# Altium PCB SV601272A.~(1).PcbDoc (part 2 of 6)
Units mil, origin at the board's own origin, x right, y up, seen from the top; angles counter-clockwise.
Board outline 8300 x 9520 mil, 8 copper layers (Top Layer, Signal Layer 1, Signal Layer 2, Signal Layer 3, Signal Layer 4, Signal Layer 5, Signal Layer 6, Bottom Layer), stack 59.2 mil thick; 551 components, 303 nets, 1611 pads, 1923 vias.
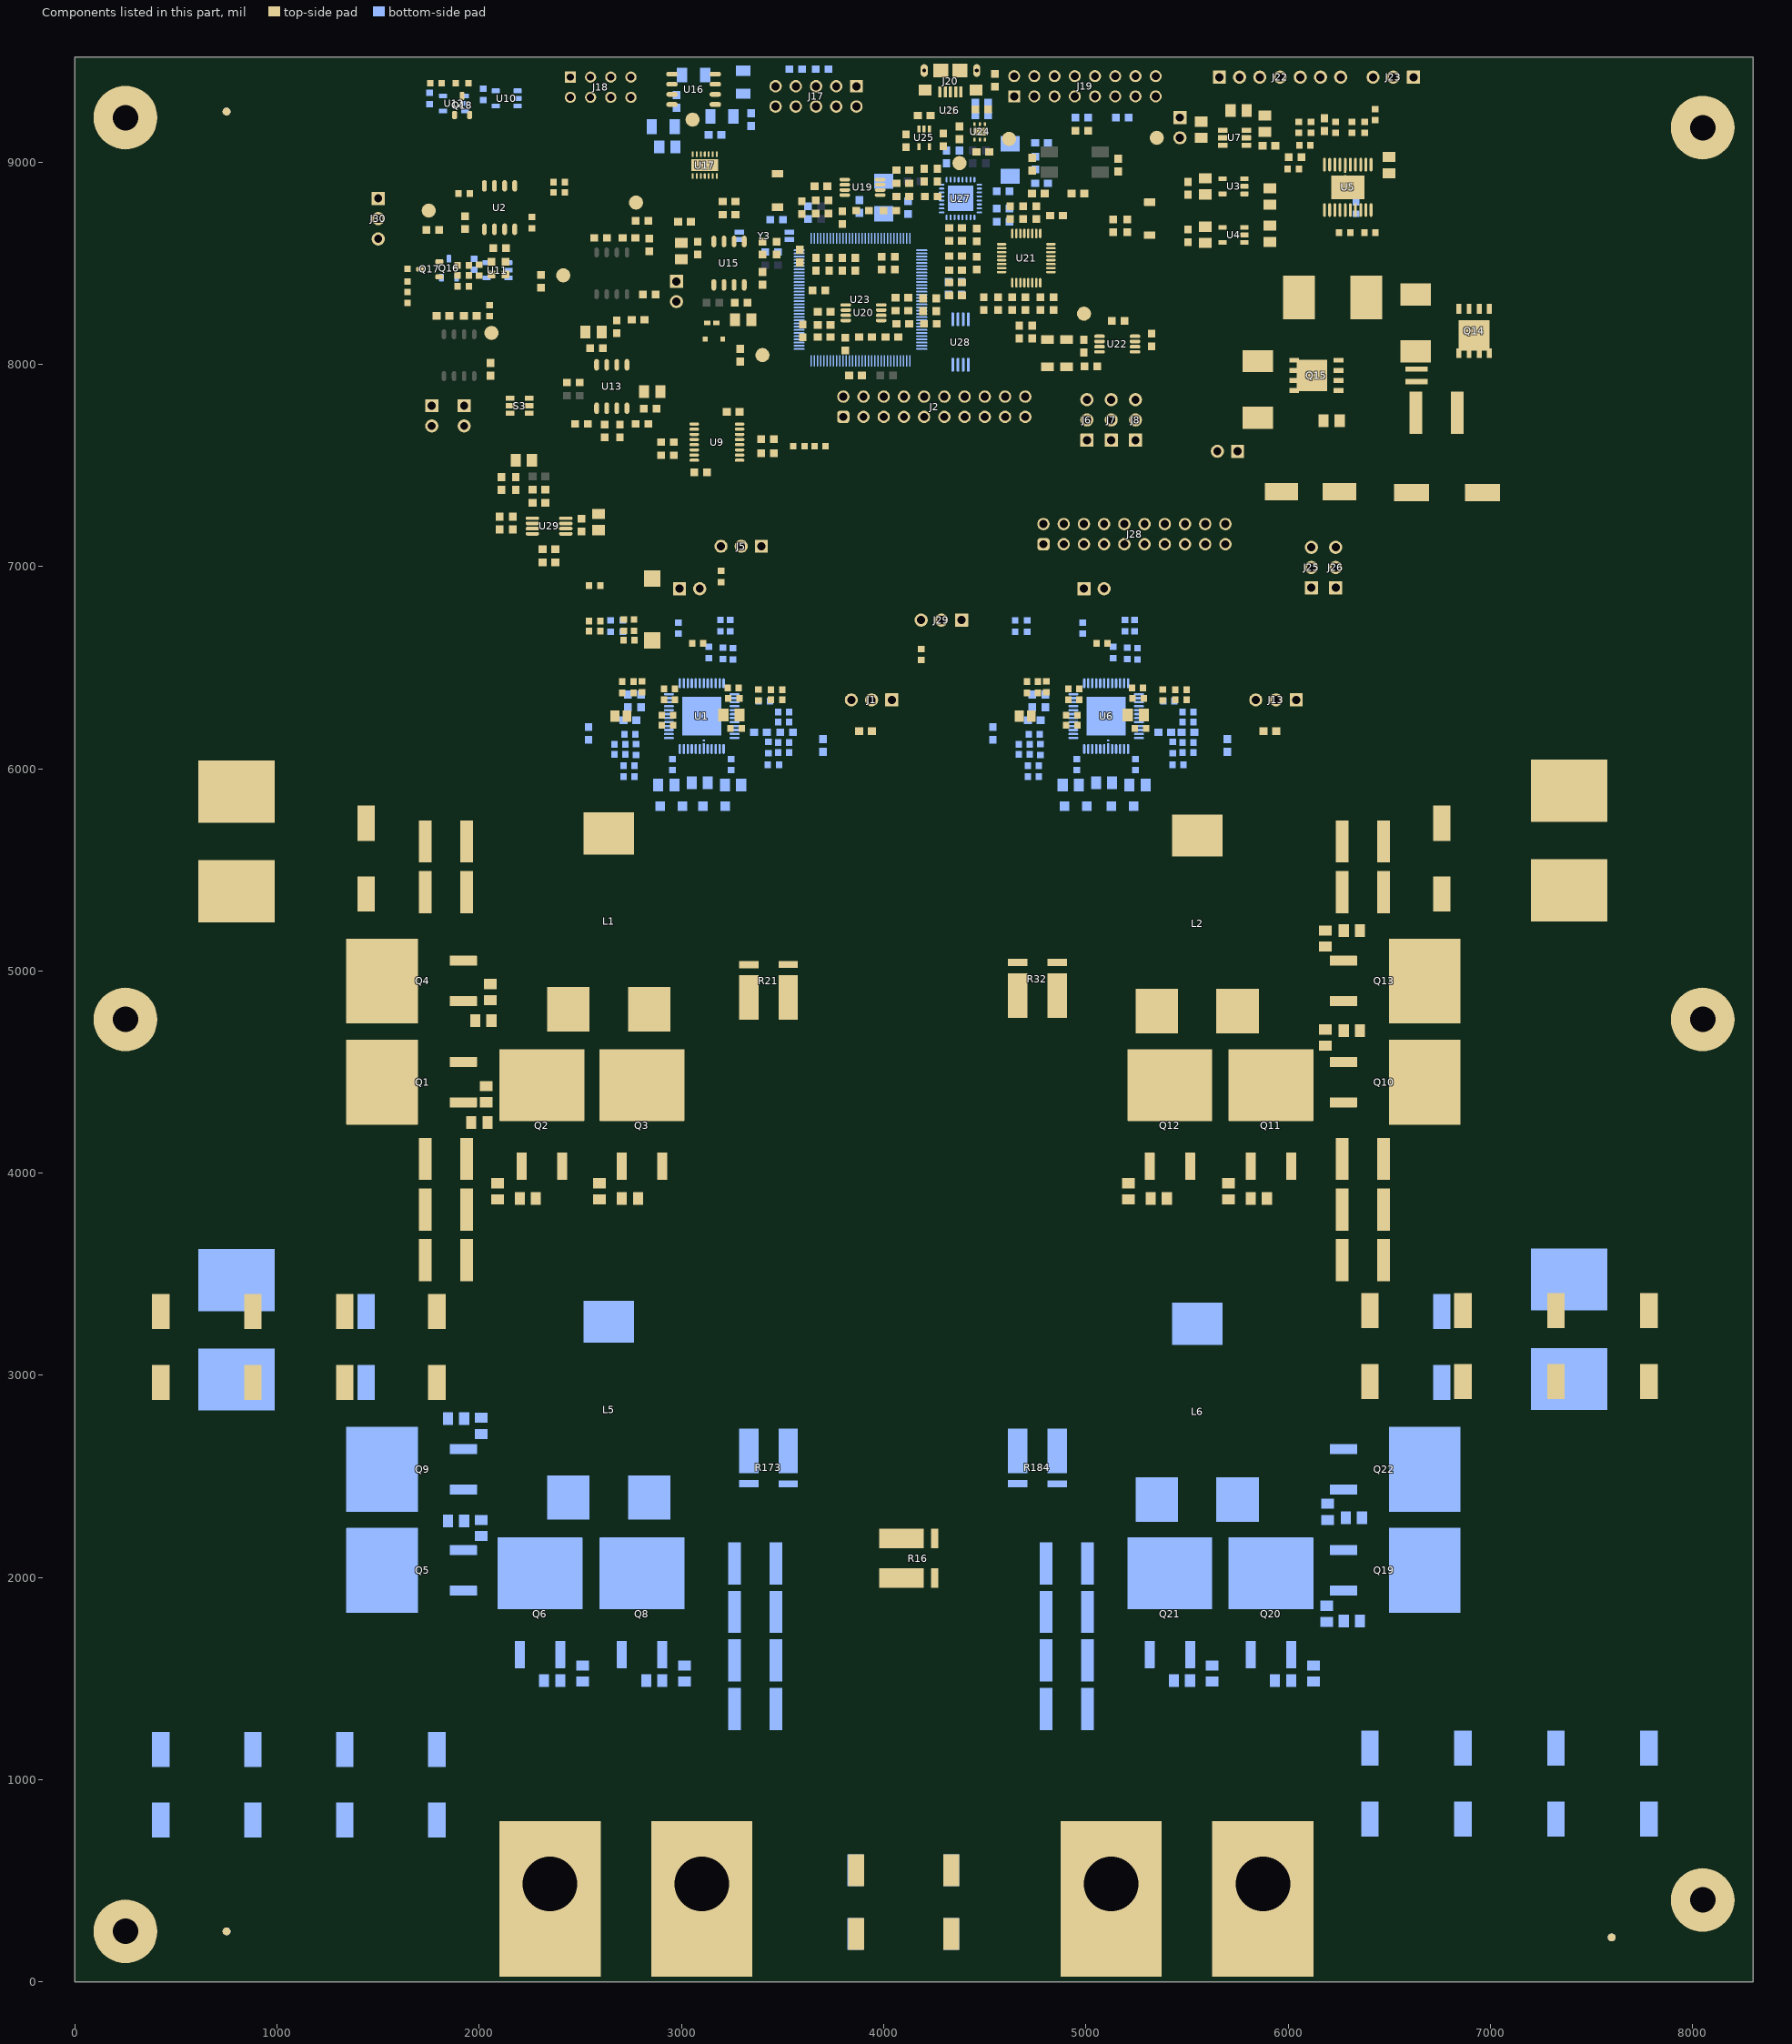
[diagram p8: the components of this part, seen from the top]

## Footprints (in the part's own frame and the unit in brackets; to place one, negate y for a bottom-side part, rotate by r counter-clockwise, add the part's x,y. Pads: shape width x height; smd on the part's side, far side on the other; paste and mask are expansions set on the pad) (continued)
D0008A_N [mm] "SOIC, 8-Leads, Body 4.9x3.9mm, Pitch 1.27mm, IPC Medium Density"
  oval 1.45x0.6 smd: 1(-2.725,1.905) 2(-2.725,0.635) 3(-2.725,-0.635) 4(-2.725,-1.905) 5(2.725,-1.905) 6(2.725,-0.635) 7(2.725,0.635) 8(2.725,1.905)
  silkscreen extent -3.3,-2.5 0.9,2.5, body extent -3,-2.45 3,2.45, height 1.63
DBV0005A_N [mm] "SOT23, 5-Leads, Body 2.9x1.6mm, Pitch 0.95mm, Lead Span 2.8mm, IPC Medium Density"
  rrect17% 1x0.6 smd: 1(-1.375,0.95) 2(-1.375,0) 3(-1.375,-0.95) 4(1.375,-0.95) 5(1.375,0.95)
  silkscreen extent -1.63,-1.55 0.38,1.55, body extent -1.42,-1.46 1.42,1.46, height 1.09
DBV0006A_M [mm] "SOT23, 6-Leads, Body 2.9x1.6mm, Pitch 0.95mm, Lead Span 2.8mm, IPC Low Density"
  rrect15% 1.2x0.65 smd: 1(-1.475,0.95) 2(-1.475,0) 3(-1.475,-0.95) 4(1.475,-0.95) 5(1.475,0) 6(1.475,0.95)
  silkscreen extent -1.83,-1.55 0.38,1.55, body extent -1.42,-1.46 1.42,1.46, height 1.12
DCK0005A_N [mm] "SOT353, 5-Leads, Body 2x1.3mm, Pitch 0.65mm, Lead Span 2.1mm, IPC Medium Density"
  rrect25% 0.85x0.4 smd: 1(-1.125,0.65) 2(-1.125,0) 3(-1.125,-0.65) 4(1.125,-0.65) 5(1.125,0.65)
  silkscreen extent -1.48,-1.02 0.55,1.1, body extent -1.14,-1 1.14,1, height 0.95
DDPAK [mil] "D2-PAK, 3-Pads, Body 9.7x10.4mm (max), TO-263AB, using Vishay Silionix recommended pad sizes"
  rrect8% 135x49.49 smd: 1(-246.06,100) 3(-246.06,-100)
  rrect1% 355x420 smd paste-181.1: 4(155.51,0)
  silkscreen extent -295,-220 344,220, body extent -295,-202 324,202, height 180
DGK0008A_N [mm] "TSOP, 8-Leads, Body 3x3mm, Pitch 0.65mm, IPC Medium Density"
  oval 1.35x0.45 smd: 1(-2.225,0.975) 2(-2.225,0.325) 3(-2.225,-0.325) 4(-2.225,-0.975) 5(2.225,-0.975) 6(2.225,-0.325) 7(2.225,0.325) 8(2.225,0.975)
  silkscreen extent -2.75,-1.55 0.95,1.55, body extent -2.45,-1.5 2.45,1.5, height 0.96
DMD0014A [mm] "TI"
  rrect40% 0.65x0.25 smd: 1(-1.375,1.5) 2(-1.375,1) 3(-1.375,0.5) 4(-1.375,0) 5(-1.375,-0.5) 6(-1.375,-1) 7(-1.375,-1.5) 8(1.375,-1.5) 9(1.375,-1) 10(1.375,-0.5) 11(1.375,0) 12(1.375,0.5) 13(1.375,1) 14(1.375,1.5)
  rrect7% 1.5x3.4 smd paste-0.75: 15(0,0)
  silkscreen extent -1.65,-2.15 1.65,2.15, body extent -1.55,-2.05 1.55,2.05, height 1.02
DRV0006A [mm] "SON, 6-Leads, Body 2x2mm, Pitch 0.65mm, Thermal Pad 1.6x1mm, TI Recommended"
  rrect33% 0.45x0.3 smd: 1(-0.975,0.65) 2(-0.975,0) 3(-0.975,-0.65) 4(0.975,-0.65) 5(0.975,0) 6(0.975,0.65)
  rrect14% 1x0.7 on Top Paste: 7(0,0.45) 7(0,-0.45)
  rrect10% 1x1.6 smd paste-0.5: 7(0,0)
  silkscreen extent -1.05,-1.2 1.05,1.2, body extent -1.05,-1.05 1.05,1.05, height 0.81
DRY0006A [mm] "PSON, 6-Leads, Body 1x1.45mm, Pitch 0.5mm, TI Recommended"
  rrect50% 0.35x0.2 smd: 1(-0.275,0.5)
  rrect50% 0.3x0.2 smd: 2(-0.3,0) 3(-0.3,-0.5) 4(0.3,-0.5) 5(0.3,0) 6(0.3,0.5)
  body extent -0.5,-0.72 0.5,0.73, height 0.58
FCC_disclaimer_stacked [mil]
FCI_10118193-0001LF [mm] "Connector, Receptacle, USB Micro B, R/A, SMT"
  rect 0.4x1.35 smd: 1(-1.3,4.125) 2(-0.65,4.125) 3(0,4.125) 4(0.65,4.125) 5(1.3,4.125)
  oval 0.9x1.6 hole 0.5 slot 1.2 at 90 deg: 6(-3.3,1.45) 7(3.3,1.45)
  rect 1.6x1.4 smd: 8(-3.2,3.9) 9(3.2,3.9)
  rect 1.9x1.7 smd: 10(-1.2,1.45) 11(1.2,1.45)
  silkscreen extent -4.3,0.2 4.3,5.4, body extent -3.93,-1.45 3.93,4.5, height 3.51
Fiducial10-20 [mm]
  round 1 smd mask+0.5: 1(0,0)
  Top Layer keep-out circle w1.178: c0,0 r0.5
HXA_JA0 [mm] "SMD, 2-Leads, Dia 10mm"
  rect 4.4x2.2 smd: 1(-4.45,0) 2(4.45,0)
  silkscreen extent -5.25,-5.25 5.25,5.25, body extent -5.55,-5.25 5.55,5.25, height 10.51
IEC_HighVoltage_Small [mil]
  silkscreen extent -107,-88 107,97
IEC_HotSurface_Small [mil]
  silkscreen extent -107,-93 107,92
Johnson_108-0740-001 [mm] "Banana Jack Uninsulated Standard Type"
  round 12 hole 6.858: 1(0,0)
  body extent -4.77,-5.43 4.75,5.57, height 2.39
KEYSTONE_2205 [mil] "THREAD HEX ALUMINUM STANDOFF 4-40, F-F 1\""
  round 1 on Mech4: 0(0,0)
  body extent -148,-128 148,128, height 1001
Label_1250x250 [mil] "Thermal Transfer Labels"
  round 1 on Mech13: 0(0,0)
  silkscreen extent -625,-125 625,125, body extent -625,-125 625,125, height 1
Microchip_32QFN-3304-5x5B [mm] "QFN, 32-Leads, Body 5x5mm, Pitch 0.5mm"
  rrect100% 0.69x0.24 smd paste-0.5 mask+0.092: 1(-2.37,1.75)
  rrect100% 0.69x0.24 smd paste-0.69 mask+0.092: 2(-2.37,1.25) 3(-2.37,0.75) 4(-2.37,0.25) 5(-2.37,-0.25) 6(-2.37,-0.75) 7(-2.37,-1.25) 8(-2.37,-1.75) 17(2.37,-1.75) 18(2.37,-1.25) 19(2.37,-0.75) 20(2.37,-0.25) 21(2.37,0.25) 22(2.37,0.75) 23(2.37,1.25) 24(2.37,1.75)
  rrect100% 0.24x0.69 smd paste-0.69 mask+0.092: 9(-1.75,-2.37) 10(-1.25,-2.37) 11(-0.75,-2.37) 12(-0.25,-2.37) 13(0.25,-2.37) 14(0.75,-2.37) 15(1.25,-2.37) 16(1.75,-2.37) 25(1.75,2.37) 26(1.25,2.37) 27(0.75,2.37) 28(0.25,2.37) 29(-0.25,2.37) 30(-0.75,2.37) 31(-1.25,2.37) 32(-1.75,2.37)
  rrect3% 3.2x3.2 smd paste-3.2: 33(0,0)
  silkscreen extent -2.65,-2.65 2.65,2.65, body extent -2.55,-2.55 2.55,2.55, height 1.01
Mill-Max_802-10-008-10-001000 [mm] "Header, 2.54 mm, 4x2, TH"
  rect 1.4x1.4 hole 0.9: 1(-3.81,1.27)
  round 1.4 hole 0.9: 2(-3.81,-1.27) 3(-1.27,1.27) 4(-1.27,-1.27) 5(1.27,1.27) 6(1.27,-1.27) 7(3.81,1.27) 8(3.81,-1.27)
  silkscreen extent -5.36,-2.54 5.08,2.54, body extent -5.08,-2.54 5.08,2.54, height 8.11
mss1278 [mm] "Coilcraft recommended land pattern.  Document 598-2 rev 04/04/13"
  rect 4x5.5 smd: 1(-4.25,0) 2(4.25,0)
  silkscreen extent -6.2,-6.2 6.2,6.2, body extent -6.15,-6.15 6.15,6.15, height 8.05
MUA08A_N [mm] "TSOP, 8-Leads, Body 3x3mm, Pitch 0.65mm, IPC Medium Density"
  oval 1.7x0.45 smd: 1(-2.1,0.975) 2(-2.1,0.325) 3(-2.1,-0.325) 4(-2.1,-0.975) 5(2.1,-0.975) 6(2.1,-0.325) 7(2.1,0.325) 8(2.1,0.975)
  silkscreen extent -2.22,-1.55 0.85,1.87, body extent -1.6,-1.6 1.6,1.6, height 1.09
MXA20A_N [mm] "TSOP, 20-Leads, Body 6.5x4.4mm, Pitch 0.65mm, Exposed Pad, IPC Medium Density"
  oval 1.7x0.35 smd: 1(-2.85,2.925) 2(-2.85,2.275) 3(-2.85,1.625) 4(-2.85,0.975) 5(-2.85,0.325) 6(-2.85,-0.325) 7(-2.85,-0.975) 8(-2.85,-1.625) 9(-2.85,-2.275) 10(-2.85,-2.925) 11(2.85,-2.925) 12(2.85,-2.275) 13(2.85,-1.625) 14(2.85,-0.975) 15(2.85,-0.325) 16(2.85,0.325) 17(2.85,0.975) 18(2.85,1.625) 19(2.85,2.275) 20(2.85,2.925)
  rect 3x4.2 smd: 21(0,0)
  silkscreen extent -2.97,-3.3 1.6,3.78, body extent -2.25,-3.3 2.25,3.3, height 1.1
Net-Tie_10mil [mil] "10mil net tie, no solder mask opening, no solder paste"
  rect 10x10 smd paste-5 mask-5: 1(-10,0) 2(10,0)
  Top Layer region: -6,5 6,5 6,-5 -6,-5
"NY PMS 440 0025 PH" [mm] "4-40 nylon screw and mounting hole"
  round 8 hole 3.2: 1(0,0)
  body extent -3.3,-3.3 3.3,3.3, height 2.69
Panduit_CXS70-14-C [mil] "Panduit"
  rect 770x500 hole 254 copper offset -74.8,0 paste-250: 1(0,0)
  body extent -960,-250 310,250, height 684
Pb-Free_Overlay_Medium [mil]
  silkscreen extent -95,-95 95,95
PBS0032A_L [mm]
  oval 1.2x0.3 smd: 1(-3.1,1.75) 2(-3.1,1.25) 3(-3.1,0.75) 4(-3.1,0.25) 5(-3.1,-0.25) 6(-3.1,-0.75) 7(-3.1,-1.25) 8(-3.1,-1.75) 17(3.1,-1.75) 18(3.1,-1.25) 19(3.1,-0.75) 20(3.1,-0.25) 21(3.1,0.25) 22(3.1,0.75) 23(3.1,1.25) 24(3.1,1.75)
  oval 0.3x1.2 smd: 9(-1.75,-3.1) 10(-1.25,-3.1) 11(-0.75,-3.1) 12(-0.25,-3.1) 13(0.25,-3.1) 14(0.75,-3.1) 15(1.25,-3.1) 16(1.75,-3.1) 25(1.75,3.1) 26(1.25,3.1) 27(0.75,3.1) 28(0.25,3.1) 29(-0.25,3.1) 30(-0.75,3.1) 31(-1.25,3.1) 32(-1.75,3.1)
  silkscreen extent -3.6,-2.53 2.53,2.53, body extent -3.51,-3.51 3.51,3.51, height 1.2
PDT0128A [mm] "Thin QFP, 128-Leads, Body 14x14mm, Pitch 0.4mm"
  oval 1.4x0.2 smd: 1(-7.7,6.2) 2(-7.7,5.8) 3(-7.7,5.4) 4(-7.7,5) 5(-7.7,4.6) 6(-7.7,4.2) 7(-7.7,3.8) 8(-7.7,3.4) 9(-7.7,3) 10(-7.7,2.6) 11(-7.7,2.2) 12(-7.7,1.8) 13(-7.7,1.4) 14(-7.7,1) 15(-7.7,0.6) 16(-7.7,0.2) 17(-7.7,-0.2) 18(-7.7,-0.6) 19(-7.7,-1) 20(-7.7,-1.4) 21(-7.7,-1.8) 22(-7.7,-2.2) 23(-7.7,-2.6) 24(-7.7,-3) 25(-7.7,-3.4) 26(-7.7,-3.8) 27(-7.7,-4.2) 28(-7.7,-4.6) 29(-7.7,-5) 30(-7.7,-5.4) 31(-7.7,-5.8) 32(-7.7,-6.2) 65(7.7,-6.2) 66(7.7,-5.8) 67(7.7,-5.4) 68(7.7,-5) 69(7.7,-4.6) 70(7.7,-4.2) 71(7.7,-3.8) 72(7.7,-3.4) 73(7.7,-3) 74(7.7,-2.6) 75(7.7,-2.2) 76(7.7,-1.8) 77(7.7,-1.4) 78(7.7,-1) 79(7.7,-0.6) 80(7.7,-0.2) 81(7.7,0.2) 82(7.7,0.6) 83(7.7,1) 84(7.7,1.4) 85(7.7,1.8) 86(7.7,2.2) 87(7.7,2.6) 88(7.7,3) 89(7.7,3.4) 90(7.7,3.8) 91(7.7,4.2) 92(7.7,4.6) 93(7.7,5) 94(7.7,5.4) 95(7.7,5.8) 96(7.7,6.2)
  oval 0.2x1.4 smd: 33(-6.2,-7.7) 34(-5.8,-7.7) 35(-5.4,-7.7) 36(-5,-7.7) 37(-4.6,-7.7) 38(-4.2,-7.7) 39(-3.8,-7.7) 40(-3.4,-7.7) 41(-3,-7.7) 42(-2.6,-7.7) 43(-2.2,-7.7) 44(-1.8,-7.7) 45(-1.4,-7.7) 46(-1,-7.7) 47(-0.6,-7.7) 48(-0.2,-7.7) 49(0.2,-7.7) 50(0.6,-7.7) 51(1,-7.7) 52(1.4,-7.7) 53(1.8,-7.7) 54(2.2,-7.7) 55(2.6,-7.7) 56(3,-7.7) 57(3.4,-7.7) 58(3.8,-7.7) 59(4.2,-7.7) 60(4.6,-7.7) 61(5,-7.7) 62(5.4,-7.7) 63(5.8,-7.7) 64(6.2,-7.7) 97(6.2,7.7) 98(5.8,7.7) 99(5.4,7.7) 100(5,7.7) 101(4.6,7.7) 102(4.2,7.7) 103(3.8,7.7) 104(3.4,7.7) 105(3,7.7) 106(2.6,7.7) 107(2.2,7.7) 108(1.8,7.7) 109(1.4,7.7) 110(1,7.7) 111(0.6,7.7) 112(0.2,7.7) 113(-0.2,7.7) 114(-0.6,7.7) 115(-1,7.7) 116(-1.4,7.7) 117(-1.8,7.7) 118(-2.2,7.7) 119(-2.6,7.7) 120(-3,7.7) 121(-3.4,7.7) 122(-3.8,7.7) 123(-4.2,7.7) 124(-4.6,7.7) 125(-5,7.7) 126(-5.4,7.7) 127(-5.8,7.7) 128(-6.2,7.7)
  silkscreen extent -7.7,-6.3 6.3,7, body extent -8,-8 8,8, height 1.07
PHP0048D_L [mm] "Thin QFP, 48-Leads, Body 7x7mm, Pitch 0.5mm, Thermal Pad 4.5x4.5mm, IPC High Density"
  rrect100% 1.25x0.3 smd: 1(-4.125,2.75) 2(-4.125,2.25) 3(-4.125,1.75) 4(-4.125,1.25) 5(-4.125,0.75) 6(-4.125,0.25) 7(-4.125,-0.25) 8(-4.125,-0.75) 9(-4.125,-1.25) 10(-4.125,-1.75) 11(-4.125,-2.25) 12(-4.125,-2.75) 25(4.125,-2.75) 26(4.125,-2.25) 27(4.125,-1.75) 28(4.125,-1.25) 29(4.125,-0.75) 30(4.125,-0.25) 31(4.125,0.25) 32(4.125,0.75) 33(4.125,1.25) 34(4.125,1.75) 35(4.125,2.25) 36(4.125,2.75)
  rrect100% 0.3x1.25 smd: 13(-2.75,-4.125) 14(-2.25,-4.125) 15(-1.75,-4.125) 16(-1.25,-4.125) 17(-0.75,-4.125) 18(-0.25,-4.125) 19(0.25,-4.125) 20(0.75,-4.125) 21(1.25,-4.125) 22(1.75,-4.125) 23(2.25,-4.125) 24(2.75,-4.125) 37(2.75,4.125) 38(2.25,4.125) 39(1.75,4.125) 40(1.25,4.125) 41(0.75,4.125) 42(0.25,4.125) 43(-0.25,4.125) 44(-0.75,4.125) 45(-1.25,4.125) 46(-1.75,4.125) 47(-2.25,4.125) 48(-2.75,4.125)
  rrect2% 4.9x4.9 smd: 49(0,0)
  silkscreen extent -4.15,3.3 -3.9,3.55, body extent -4.51,-4.51 4.51,4.51, height 1.2
PogoPad [mil] "No Solder Paste"
  round 70 smd paste-35: 1(0,0)
PowerPAK_SO-8 [mil] "Vishay PowerPAK SO-8, Body 5.3x6.0mm (max), Pitch 1.27mm, IPC Medium Density"
  rect 50x24 smd mask+2.99: 1(-109.5,75) 2(-109.5,25) 3(-109.5,-25) 4(-109.5,-75)
  rect 48x24 smd mask+2.99: 5(109.5,-75) 8(109.5,75)
  rect 48x24 smd paste-12 mask+2.99: 6(109.5,-25) 7(109.5,25)
  rect 150x154 smd paste-75 mask+2.99: 9(22.5,0)
  silkscreen extent -114,-104 62,113, body extent -121,-102 121,102, height 43
PW0016A_L [mm] "TSOP, 16-Leads, Body 5x4.4mm, Pitch 0.65mm, IPC High Density"
  oval 1.2x0.4 smd: 1(-2.85,2.275) 2(-2.85,1.625) 3(-2.85,0.975) 4(-2.85,0.325) 5(-2.85,-0.325) 6(-2.85,-0.975) 7(-2.85,-1.625) 8(-2.85,-2.275) 9(2.85,-2.275) 10(2.85,-1.625) 11(2.85,-0.975) 12(2.85,-0.325) 13(2.85,0.325) 14(2.85,0.975) 15(2.85,1.625) 16(2.85,2.275)
  silkscreen extent -2,-2.55 1.85,2.55, body extent -3.21,-2.5 3.21,2.5, height 1
RES_WSL2726 [mm] "Vishay Dale"
  rect 2.44x5.6 smd: 1(-2.48,-2.07) 2(2.48,-2.065)
  rect 2.44x0.89 smd: 3(-2.48,2.065) 4(2.48,2.07)
  body extent -3.55,-4.45 3.55,2.45, height 3.22
Samtec_HTSW-102-07-G-S [mm] "Samtec 100mil, 1x2, 230 mil above insulator"
  rrect6% 1.65x1.65 hole 1.016: 1(-1.27,0)
  round 1.65 hole 1.016: 2(1.27,0)
  silkscreen extent -3.3,-1.27 2.54,1.27, body extent -2.54,-1.27 2.54,1.27, height 8.38
Samtec_HTSW-103-07-G-S [mm] "Samtec 100mil, 1x3, 230 mil above insulator"
  rrect6% 1.65x1.65 hole 1.016: 1(-2.54,0)
  round 1.65 hole 1.016: 2(0,0) 3(2.54,0)
  silkscreen extent -4.57,-1.27 3.81,1.27, body extent -3.81,-1.27 3.81,1.27, height 8.38
Seiko_SSP-T [mm] "Seiko Instruments"
  rect 0.6x1.2 smd: 1(-0.45,3.15) 2(-0.45,-3.15) 3(0.45,-3.15) 4(0.45,3.15)
  silkscreen extent -1.23,-2 0.75,2.29, body extent -0.75,-3.35 0.75,3.35, height 1.41
SMC [mil] "Molded Diode, 2-Leads, Body 6.9x5.8mm, IPC Medium Density, based on OnSemi component dimensions and land patterns"
  rect 110x150 smd: 1(-140.49,0) 2(140.49,0)
  silkscreen extent -221,-124 189,123, body extent -156,-116 156,116, height 91
SOD-123F [mm] "NXP recommended land pattern"
  rect 1.2x1.2 smd paste-0.05: 1(-1.4,0) 2(1.4,0)
  silkscreen extent -2.64,-1.12 2.01,1.12, body extent -1.8,-0.85 1.8,0.85, height 1.2
SOD-323 [mm] "NXP recommended land pattern"
  rect 0.6x0.6 smd paste-0.05: 1(-1.1,0) 2(1.1,0)
  silkscreen extent -2.06,-0.86 1.53,0.86, body extent -1.3,-0.67 1.3,0.68, height 1.1
SOD-523 [mm] "NXP Semiconductor recommended land pattern, nominal STEP model"
  rect 0.8x0.6 smd paste-0.05: 1(-0.55,0) 2(0.55,0)
  silkscreen extent -1.65,-0.66 1.2,0.66, body extent -0.8,-0.4 0.8,0.4, height 0.72
SOT23-6_N [mm] "SOT23, 6-Leads, Body 2.9x1.6mm, Pitch 0.95mm, Lead Span 2.7mm, IPC Medium Density"
  rect 1.1x0.65 smd: 1(-1.2,0.95) 2(-1.2,0) 3(-1.2,-0.95) 4(1.2,-0.95) 5(1.2,0) 6(1.2,0.95)
  silkscreen extent -1.33,-1.55 0.25,1.95, body extent -0.9,-1.55 0.9,1.55, height 1.45
SOT-23 [mm] "SOT23, 3-Leads, Body 2.9x1.3mm, Pitch 0.95mm, Lead Span 2.5mm, IPC Medium Density"
  rrect50% 1x0.6 smd: 1(-1.2,0.95) 2(-1.2,-0.95) 3(1.2,0)
  silkscreen extent -1.62,-1.5 0.7,1.5, body extent -1.16,-1.45 1.21,1.45, height 1
SULLINS_PEC10DAAN [mm] "SULLINS"
  rrect50% 1.55x1.55 hole 1.016: 1(-1.27,11.43)
  round 1.55 hole 1.016: 2(1.27,11.43) 3(-1.27,8.89) 4(1.27,8.89) 5(-1.27,6.35) 6(1.27,6.35) 7(-1.27,3.81) 8(1.27,3.81) 9(-1.27,1.27) 10(1.27,1.27) 11(-1.27,-1.27) 12(1.27,-1.27) 13(-1.27,-3.81) 14(1.27,-3.81) 15(-1.27,-6.35) 16(1.27,-6.35) 17(-1.27,-8.89) 18(1.27,-8.89) 19(-1.27,-11.43) 20(1.27,-11.43)
  silkscreen extent -2.9,-12.7 2.54,12.7, body extent -2.54,-12.7 2.54,12.7, height 8.38
Sullins_xxxC008DAAN [mm] "Header, 2.54mm, 8x2, TH"
  rect 1.5x1.5 hole 1: 1(-1.27,8.89)
  round 1.5 hole 1: 2(1.27,8.89) 3(-1.27,6.35) 4(1.27,6.35) 5(-1.27,3.81) 6(1.27,3.81) 7(-1.27,1.27) 8(1.27,1.27) 9(-1.27,-1.27) 10(1.27,-1.27) 11(-1.27,-3.81) 12(1.27,-3.81) 13(-1.27,-6.35) 14(1.27,-6.35) 15(-1.27,-8.89) 16(1.27,-8.89)
  silkscreen extent -2.5,-10.16 2.5,10.6, body extent -2.5,-10.16 2.5,10.16, height 8.34
SW_TL1015AF160QG#1 [mm] "E-Switch"
  rrect11% 0.95x1.4 smd: 1(-2.075,0) 2(2.075,0)
  body extent -2.3,-1.5 2.3,1.5, height 2
SW_TL1015AF160QG#2 [mm] "E-Switch"
  rect 0.95x1.4 smd: 1(-2.1,0) 2(2.1,0)
  silkscreen extent -2,-1.5 2,1.5, body extent -2.3,-1.5 2.3,1.5, height 2
TP_25MIL-SMT [mil]
  rect 80x80 smd mask-2.5: 1(0,0)
TSSOP-8 [mm] "TSSOP, 8-Leads, Body 3.1x4.5mm (max), Pitch 0.65mm, IPC Medium Density"
  rrect50% 1.7x0.35 smd: 1(-2.85,0.975) 2(-2.85,0.325) 3(-2.85,-0.325) 4(-2.85,-0.975) 5(2.85,-0.975) 6(2.85,-0.325) 7(2.85,0.325) 8(2.85,0.975)
  silkscreen extent -2.97,-1.55 1.6,1.83, body extent -3.2,-1.55 3.2,1.55, height 1.07
TSW-107-07-G-S [mm] "Samtec 100mil, 1x7, 230 mil above insulator"
  rrect6% 1.65x1.65 hole 1.016: 1(-7.62,0)
  round 1.65 hole 1.016: 2(-5.08,0) 3(-2.54,0) 4(0,0) 5(2.54,0) 6(5.08,0) 7(7.62,0)
  silkscreen extent -8.89,-1.27 8.89,1.65, body extent -8.89,-1.27 8.89,1.27, height 8.38
WE-HCF_2818 [mm] "SMD, 3-Leads, Body 28.5x19.5mm"
  rect 5.59x5.33 smd: 1(-14.465,5.075) 2(-14.465,-5.075)
  rect 5.28x6.35 smd: MP(7.61,0)
  silkscreen extent -11,-14.25 9.75,14.25, body extent -16.65,-14.25 11.35,14.25, height 18.5
WL-SMCW_GREEN [mm] "WURTH"
  rect 0.8x0.8 smd: 1(-0.8,0) 2(0.8,0)
  silkscreen extent -1.9,-0.8 1.2,0.8, body extent -0.85,-0.45 0.85,0.45, height 0.8
WL-SMCW_YELLOW [mm] "WURTH"
  rect 0.8x0.8 smd: 1(-0.8,0) 2(0.8,0)
  silkscreen extent -1.9,-0.8 1.2,0.8, body extent -0.85,-0.45 0.85,0.45, height 0.8
XTAL_ABM3 [mm] "Abracon recommended land pattern 12.28.10"
  rect 1.9x2.4 smd: 1(-2.05,0) 2(2.05,0)
  silkscreen extent -2.67,-1.78 2.67,1.78, body extent -2.6,-1.7 2.6,1.7, height 1.3

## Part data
C1 C3 C5 C8 C16 C19 C31 C204: "CAP, CERM, 1000 pF, 100 V, +/- 5%, C0G/NP0, 0603", Cap_Case=0603, Manufacturer=TDK, Supplier Part Number 1=445-2312-1-ND, TempCo=C0G/NP0, Tolerance_%=5, Value1="0.0589 ohm", Value2=100V, ValueDisplayed=1000pF
C2 C9 C14 C17 C197 C205: "CAP, CERM, 0.01 µF, 100 V, +/- 10%, X7R, 0603", Cap_Case=0603, Manufacturer=AVX, Supplier Part Number 1=478-1205-1-ND, TempCo=X7R, Tolerance_%=10, Value1="0.098 ohm", Value2=100V, ValueDisplayed=0.01µF
C4 C15 C30 C201: "CAP, CERM, 0.015 µF, 25 V, +/- 10%, X7R, 0603", Cap_Case=0603, Manufacturer=MuRata, Supplier Part Number 1=81-GRM39X153K25D, TempCo=X7R, Tolerance_%=10, Value1=Unknown, Value2=25V, ValueDisplayed=0.015µF
C6 C33 C34 C35 C36 C37: "CAP, CERM, 1 µF, 100 V, +/- 10%, X7S, 0805", Cap_Case=0805, Manufacturer=TDK, Supplier Part Number 1=445-5205-1-ND, TempCo=X7S, Tolerance_%=10, Value1=Unknown, Value2=100V, ValueDisplayed=1µF
C7 C12 C192 C195: "CAP, CERM, 0.22 µF, 50 V, +/- 10%, X7R, 0603", Cap_Case=0603, Manufacturer=TDK, Supplier Part Number 1=445-7408-1-ND, TempCo=X7R, Tolerance_%=10, Value1=Unknown, Value2=50V, ValueDisplayed=0.22µF
C10 C43 C193: "CAP, CERM, 2.2 µF, 16 V, +/- 10%, X7R, 0805", Cap_Case=0805, Manufacturer=TDK, Supplier Part Number 1=445-1420-1-ND, TempCo=X7R, Tolerance_%=10, Value1="0.0049 ohm", Value2=16V, ValueDisplayed=2.2µF
C11 C47 C48 C173 C179 C180 C182 C183 C194: "CAP, CERM, 1 µF, 25 V, +/- 10%, X7R, 0603", Cap_Case=0603, Manufacturer=MuRata, Supplier Part Number 1=490-5307-1-ND, TempCo=X7R, Tolerance_%=10, Value1=Unknown, Value2=25V, ValueDisplayed=1µF
C13 C72 C73 C74 C75 C82 C83 C102 C190 C191 C196 C199 C200 C202 C203: "CAP, CERM, 100 pF, 50 V, +/- 5%, C0G/NP0, 0603", Cap_Case=0603, Manufacturer=Kemet, Supplier Part Number 1=399-1061-1-ND, TempCo=C0G/NP0, Tolerance_%=5, Value1=Unknown, Value2=50V, ValueDisplayed=100pF
C18 C32 C211 C217: "CAP, AL, 100 µF, 100 V, +/- 20%, 0.24 ohm, SMD", Cap_Case=LH0, Manufacturer=Chemi-Con, Supplier Part Number 1=565-2344-1-ND, Tolerance_%=20, Value1="0.24 ohm", Value2=100V, ValueDisplayed=100µF
C20 C21 C54 C55: "CAP, AL, 180 µF, 50 V, +/- 20%, 0.019 ohm, SMD", Cap_Case=10x12.7mm, Manufacturer=Nichicon, Supplier Part Number 1=493-13774-1-ND, Tolerance_%=20, Value1="0.019 ohm", Value2=50V, ValueDisplayed=180µF
C22 C23 C24 C25 C26 C27 C28 C29 C62 C63 C64 C65 C66 C67 C68 C69 C70 C71: "CAP, CERM, 4.7 µF, 100 V, +/- 20%, X7R, 2220", Cap_Case=2220, Manufacturer=TDK, Supplier Part Number 1=445-1450-1-ND, TempCo=X7R, Tolerance_%=20, Value1="0.0015 ohm", Value2=100V, ValueDisplayed=4.7µF
C38: "CAP, AL, 22 µF, 100 V, +/- 20%, 0.55 ohm, SMD", Cap_Case=JA0, Manufacturer=Chemi-Con, Supplier Part Number 1=565-2341-1-ND, Tolerance_%=20, Value1="0.55 ohm", Value2=100V, ValueDisplayed=22µF
C39: "CAP, CERM, 10 µF, 100 V, +/- 20%, X7S,", Cap_Case=2220, Manufacturer=TDK, Supplier Part Number 1=445-5212-1-ND, TempCo=X7S, Tolerance_%=20, Value1="0.005 ohm", Value2=100V, ValueDisplayed=10µF
C40: "CAP, CERM, 0.1 µF, 100 V, +/- 10%, X7R, 0805", Cap_Case=0805, Manufacturer=TDK, Supplier Part Number 1=445-1418-1-ND, TempCo=X7R, Tolerance_%=10, Value1="0.0158 ohm", Value2=100V, ValueDisplayed=0.1µF
C41 C44 C84 C91 C93 C94 C189: "CAP, CERM, 0.1 µF, 100 V, +/- 10%, X7R, 0603", Cap_Case=0603, Manufacturer=MuRata, Supplier Part Number 1=490-3285-1-ND, TempCo=X7R, Tolerance_%=10, Value1=Unknown, Value2=100V, ValueDisplayed=0.1µF
C42: "CAP, Aluminum Polymer, 180 µF, 16 V, +/- 20%, 0.016 ohm, HC0 SMD", Cap_Case=HC0, Manufacturer=Chemi-Con, Supplier Part Number 1=565-3078-1-ND, Tolerance_%=20, Value1="0.016 ohm", Value2=16V, ValueDisplayed=180µF
C45: "CAP, CERM, 330 pF, 100 V, +/- 5%, C0G/NP0, 0603", Cap_Case=0603, Manufacturer=TDK, Supplier Part Number 1=445-2309-1-ND, TempCo=C0G/NP0, Tolerance_%=5, Value1="0.1269 ohm", Value2=100V, ValueDisplayed=330pF
C46: "CAP, CERM, 0.056 µF, 50 V, +/- 10%, X7R, 0603", Cap_Case=0603, Manufacturer=MuRata, Supplier Part Number 1=81-GRM188R71H563KA93, TempCo=X7R, Tolerance_%=10, Value1=Unknown, Value2=50V, ValueDisplayed=0.056µF
C49: "CAP, CERM, 1500 pF, 100 V, +/- 5%, C0G/NP0, 0603", Cap_Case=0603, Manufacturer=MuRata, Supplier Part Number 1=GRM1885C2A152JA01D-ND, TempCo=C0G/NP0, Tolerance_%=5, Value1=Unknown, Value2=100V, ValueDisplayed=1500pF
C50 C51 C52 C53 C56 C57 C58 C59 C60 C61 C206 C207 C208 C209 C210 C212 C213 C214 C215 C216: "CAP, Aluminum Polymer, 39 µF, 80 V, +/- 20%, 0.035 ohm, AEC-Q200 Grade 1, D10xL10mm SMD", Cap_Case=10X10mm, Manufacturer=Chemi-Con, Supplier Part Number 1=565-4174-1-ND, Tolerance_%=20, Value1="0.035 ohm", Value2=80V, ValueDisplayed=39µF
C76 C77 C78: library part CMP-0007891-2, "CAP, CERM, 1 uF, 100 V, +/- 10%, X7S, 0805", Cap_Case=0805, Manufacturer=TDK, PartNumber=C2012X7S2A105K125AB, Supplier Part Number 1=445-5205-1-ND, TempCo=X7S, Tolerance_%=10%, Value1="0.008255 ohm", Value2=100V, ValueDisplayed=1uF
C79 C85 C137 C139 C140: library part CMP-0006727-4, "CAP, CERM, 0.01 uF, 100 V, +/- 10%, X7R, 0603", Cap_Case=0603, Manufacturer=AVX, PartNumber=06031C103KAT2A, Supplier Part Number 1=478-1205-1-ND, TempCo=X7R, Tolerance_%=10%, Value1="0.098 ohm", Value2=100V, ValueDisplayed=0.01uF
C80 C81 C95 C198: "CAP, CERM, 0.47 µF, 16 V, +/- 10%, X7R, 0603", Cap_Case=0603, Manufacturer=MuRata, Supplier Part Number 1=490-3295-1-ND, TempCo=X7R, Tolerance_%=10, Value1=Unknown, Value2=16V, ValueDisplayed=0.47µF
C87: library part CMP-0006839-4, "CAP, CERM, 10 pF, 50 V, +/- 5%, C0G/NP0, 0603", Cap_Case=0603, Manufacturer=Kemet, Supplier Part Number 1=399-1049-1-ND, TempCo=C0G/NP0, Tolerance_%=5%, Value1=Unknown, Value2=50V, ValueDisplayed=10pF
C89: library part CMP-0007010-5, "CAP, CERM, 0.1 uF, 50 V, +/- 10%, X5R, 0603", Cap_Case=0603, Manufacturer=TDK, Supplier Part Number 1=445-7456-1-ND, TempCo=X5R, Tolerance_%=10%, Value1="0.0296 ohm", Value2=50V, ValueDisplayed=0.1uF
C90: library part CMP-0007122-5, "CAP, CERM, 10 uF, 16 V, +/- 20%, X5R, 0603", Cap_Case=0603, Manufacturer="Taiyo Yuden", Supplier Part Number 1=587-3238-1-ND, TempCo=X5R, Tolerance_%=20%, Value1=Unknown, Value2=16V, ValueDisplayed=10uF
C96 C97 C99 C106 C108 C111 C112 C116 C119 C133 C135 C146: library part CMP-0006752-5, "CAP, CERM, 0.1 uF, 25 V, +/- 5%, X7R, 0603", Cap_Case=0603, Manufacturer=AVX, PartNumber=06033C104JAT2A, Supplier Part Number 1=478-3713-1-ND, TempCo=X7R, Tolerance_%=5%, Value1="0.05 ohm", Value2=25V, ValueDisplayed=0.1uF
C98: library part CMP-0006841-4, "CAP, CERM, 100 pF, 50 V, +/- 5%, C0G/NP0, 0603", Cap_Case=0603, Manufacturer=Kemet, PartNumber=C0603C101J5GACTU, Supplier Part Number 1=399-1061-1-ND, TempCo=C0G/NP0, Tolerance_%=5%, Value1=Unknown, Value2=50V, ValueDisplayed=100pF
C100 C104 C105 C218: library part CMP-0007383-5, "CAP, CERM, 0.015 uF, 16 V, +/- 10%, X7R, 0603", Cap_Case=0603, Manufacturer=MuRata, PartNumber=GRM188R71C153KA01D, Supplier Part Number 1=81-GRM188R71C153KA, TempCo=X7R, Tolerance_%=10%, Value1=Unknown, Value2=16V, ValueDisplayed=0.015uF
C107 C109 C117 C120: library part CMP-0008315-2, "CAP, CERM, 10 uF, 10 V, +/- 10%, X7R, 0805", Cap_Case=0805, Manufacturer=MuRata, PartNumber=GRM21BR71A106KE51L, Supplier Part Number 1=490-3905-1-ND, TempCo=X7R, Tolerance_%=10%, Value1="0.003 ohm", Value2=10V, ValueDisplayed=10uF
C110: library part CMP-0007143-4, "CAP, CERM, 0.01 uF, 50 V, +/- 10%, X7R, AEC-Q200 Grade 1, 0603", Cap_Case=0603, Manufacturer=MuRata, Supplier Part Number 1=490-4778-1-ND, TempCo=X7R, Tolerance_%=10%, Value1=Unknown, Value2=50V, ValueDisplayed=0.01uF
C113 C114 C121: library part CMP-0007170-4, "CAP, CERM, 10 pF, 50 V, +/- 5%, C0G/NP0, 0603", Cap_Case=0603, Manufacturer=MuRata, PartNumber=GRM1885C1H100JA01D, Supplier Part Number 1=490-1403-1-ND, TempCo=C0G/NP0, Tolerance_%=5%, Value1=Unknown, Value2=50V, ValueDisplayed=10pF
C115: library part CMP-0007334-5, "CAP, CERM, 0.1 uF, 16 V, +/- 10%, X5R, 0603", Cap_Case=0603, Manufacturer=MuRata, PartNumber=GRM188R61C104KA01D, Supplier Part Number 1=GRM188R61C104KA01D-ND, TempCo=X5R, Tolerance_%=10%, Value1=Unknown, Value2=16V, ValueDisplayed=0.1uF
C118: library part CMP-0007302-5, "CAP, CERM, 1 uF, 6.3 V, +/- 10%, X5R, 0603", Cap_Case=0603, Manufacturer=MuRata, PartNumber=GRM188R60J105KA01D, Supplier Part Number 1=490-1550-1-ND, TempCo=X5R, Tolerance_%=10%, Value1=Unknown, Value2=6.3V, ValueDisplayed=1uF
C122 C123 C125 C126: library part CMP-0008509-2, "CAP, CERM, 1 uF, 25 V, +/- 10%, X7R, 1206", Cap_Case=1206, Manufacturer=AVX, PartNumber=12063C105KAT2A, Supplier Part Number 1=478-1567-1-ND, TempCo=X7R, Tolerance_%=10%, Value1="0.013 ohm", Value2=25V, ValueDisplayed=1uF
C124: library part CMP-0008273-1, "CAP, CERM, 10 uF, 35 V, +/- 10%, X6S, 0805", Cap_Case=0805, Manufacturer=MuRata, PartNumber=GRM21BC8YA106KE11L, Supplier Part Number 1=490-10504-1-ND, TempCo=X6S, Tolerance_%=10%, Value1=Unknown, Value2=35V, ValueDisplayed=10uF
C127 C128: library part CMP-0006857-4, "CAP, CERM, 0.1 uF, 16 V, +/- 5%, X7R, 0603", Cap_Case=0603, Manufacturer=Kemet, PartNumber=C0603C104J4RACTU, Supplier Part Number 1=399-1097-1-ND, TempCo=X7R, Tolerance_%=5%, Value1=Unknown, Value2=16V, ValueDisplayed=0.1uF
C131 C132: library part CMP-0006903-4, "CAP, CERM, 0.22 uF, 16 V, +/- 10%, X7R, 0603", Cap_Case=0603, Manufacturer=Kemet, PartNumber=C0603C224K4RACTU, Supplier Part Number 1=399-5619-1-ND, TempCo=X7R, Tolerance_%=10%, Value1=Unknown, Value2=16V, ValueDisplayed=0.22uF
C134 C136 C138 C141 C145 C155 C156 C160 C161 C188: library part CMP-0007405-4, "CAP, CERM, 1 uF, 25 V, +/- 10%, X7R, 0603", Cap_Case=0603, Manufacturer=MuRata, PartNumber=GRM188R71E105KA12D, Supplier Part Number 1=490-5307-1-ND, TempCo=X7R, Tolerance_%=10%, Value1=Unknown, Value2=25V, ValueDisplayed=1uF
C142 C144 C150 C154: library part CMP-0006732-4, "CAP, CERM, 1500 pF, 100 V, +/- 5%, X7R, 0603", Cap_Case=0603, Manufacturer=AVX, PartNumber=06031C152JAT2A, Supplier Part Number 1=478-3703-1-ND, TempCo=X7R, Tolerance_%=5%, Value1="0.229 ohm", Value2=100V, ValueDisplayed=1500pF
C143 C151: library part CMP-0007481-5, "CAP, CERM, 3900 pF, 100 V, +/- 10%, X7R, 0603", Cap_Case=0603, Manufacturer=MuRata, Supplier Part Number 1=GRM188R72A392KA01D-ND, TempCo=X7R, Tolerance_%=10%, Value1=Unknown, Value2=100V, ValueDisplayed=3900pF
C147 C148: library part CMP-0007204-4, "CAP, CERM, 2700 pF, 50 V, +/- 5%, C0G/NP0, 0603", Cap_Case=0603, Manufacturer=MuRata, PartNumber=GRM1885C1H272JA01D, Supplier Part Number 1=490-3283-1-ND, TempCo=C0G/NP0, Tolerance_%=5%, Value1=Unknown, Value2=50V, ValueDisplayed=2700pF
C149: library part CMP-0006761-4, "CAP, CERM, 10 pF, 50 V, +/- 5%, C0G/NP0, 0603", Cap_Case=0603, Manufacturer=AVX, PartNumber=06035A100JAT2A, Supplier Part Number 1=478-1163-1-ND, TempCo=C0G/NP0, Tolerance_%=5%, Value1="0.403 ohm", Value2=50V, ValueDisplayed=10pF
C152 C153: library part CMP-0007193-4, "CAP, CERM, 20 pF, 50 V, +/- 5%, C0G/NP0, 0603", Cap_Case=0603, Manufacturer=MuRata, Supplier Part Number 1=490-1410-1-ND, TempCo=C0G/NP0, Tolerance_%=5%, Value1=Unknown, Value2=50V, ValueDisplayed=20pF
C157: library part CMP-0006723-4, "CAP, CERM, 1000 pF, 100 V, +/- 5%, X7R, 0603", Cap_Case=0603, Manufacturer=AVX, PartNumber=06031C102JAT2A, Supplier Part Number 1=478-3698-1-ND, TempCo=X7R, Tolerance_%=5%, Value1="0.276 ohm", Value2=100V, ValueDisplayed=1000pF
C158 C159: library part CMP-0008649-2, "CAP, CERM, 100 uF, 10 V, +/- 20%, X5R, 1206_190", Cap_Case=1206_190, Manufacturer=TDK, PartNumber=C3216X5R1A107M160AC, Supplier Part Number 1=445-6007-1-ND, TempCo=X5R, Tolerance_%=20%, Value1="0.002838 ohm", Value2=10V, ValueDisplayed=100uF
C162 C164: "CAP, CERM, 12 pF, 50 V, +/- 5%, C0G/NP0, 0603", Cap_Case=0603, Manufacturer=Kemet, Supplier Part Number 1=399-1050-1-ND, TempCo=C0G/NP0, Tolerance_%=5, Value1=Unknown, Value2=50V, ValueDisplayed=12pF
C163 C165 C166 C167 C168 C169 C174 C176 C177 C178 C187: "CAP, CERM, 0.1 µF, 25 V, +/- 5%, X7R, 0603", Cap_Case=0603, Manufacturer=AVX, Supplier Part Number 1=478-3713-1-ND, TempCo=X7R, Tolerance_%=5, Value1="0.05 ohm", Value2=25V, ValueDisplayed=0.1µF
C170 C171: "CAP, CERM, 6.8 pF, 50 V, +/- 4%, C0G/NP0, 0603", Cap_Case=0603, Manufacturer=AVX, Supplier Part Number 1=478-1161-1-ND, TempCo=C0G/NP0, Tolerance_%=4, Value1="0.505 ohm", Value2=50V, ValueDisplayed=6.8pF
C172 C175: "CAP, CERM, 2.2 µF, 35 V, +/- 10%, X5R, 0603", Cap_Case=0603, Manufacturer=MuRata, Supplier Part Number 1=490-7204-6-ND, TempCo=X5R, Tolerance_%=10, Value1=Unknown, Value2=35V, ValueDisplayed=2.2µF
C181 C184: "CAP, CERM, 1000 pF, 100 V, +/- 5%, X7R, 0603", Cap_Case=0603, Manufacturer=AVX, Supplier Part Number 1=478-3698-1-ND, TempCo=X7R, Tolerance_%=5, Value1="0.276 ohm", Value2=100V, ValueDisplayed=1000pF
C185 C186: "CAP, CERM, 27 pF, 50 V, +/- 5%, C0G/NP0, 0603", Cap_Case=0603, Manufacturer=AVX, Supplier Part Number 1=478-1168-1-ND, TempCo=C0G/NP0, Tolerance_%=5, Value1="0.232 ohm", Value2=50V, ValueDisplayed=27pF
C221: "CAP, CERM, 0.22 µF, 10 V, +/- 10%, X5R, 0603", Cap_Case=0603, Manufacturer=MuRata, Supplier Part Number 1=490-1537-1-ND, TempCo=X5R, Tolerance_%=10, Value1=Unknown, Value2=10V, ValueDisplayed=0.22µF
C222: "CAP, CERM, 4.7 µF, 10 V, +/- 20%, X5R, 0603", Cap_Case=0603, Manufacturer=MuRata, TempCo=X5R, Tolerance_%=20, Value1=Unknown, Value2=10V, ValueDisplayed=4.7µF
C223 C228 C229: "CAP, CERM, 10 µF, 10 V, +/- 20%, X5R, 0603", Cap_Case=0603, Manufacturer=MuRata, TempCo=X5R, Tolerance_%=20, Value1=Unknown, Value2=10V, ValueDisplayed=10µF
C224 C226: "CAP, CERM, 22 µF, 6.3 V, +/- 20%, X5R, 0603", Cap_Case=0603, Manufacturer=MuRata, Supplier Part Number 1=490-7611-1-ND, TempCo=X5R, Tolerance_%=20, Value1=Unknown, Value2=6.3V, ValueDisplayed=22µF
C225: "CAP, CERM, 0.1 µF, 16 V, +/- 10%, X5R, 0603", Cap_Case=0603, Manufacturer=MuRata, Supplier Part Number 1=GRM188R61C104KA01D-ND, TempCo=X5R, Tolerance_%=10, Value1=Unknown, Value2=16V, ValueDisplayed=0.1µF
C227: "CAP, CERM, 0.47 µF, 25 V, +/- 10%, X7R, 0603", Cap_Case=0603, Manufacturer=MuRata, Supplier Part Number 1=490-3291-1-ND, TempCo=X7R, Tolerance_%=10, Value1=Unknown, Value2=25V, ValueDisplayed=0.47µF
CC CV DVDD_3V3 IBAT V1.8 V-5 VBAT VREF_ADC VREF_DAC VREF_LV: library part PogoPad, "Pad for Pogo Pin Connector"
CS1 CS2: library part CMP-0078143-2, "TEST POINT.  No entry in BOM.", Manufacturer=N/A
D1 D2 D4 D10: "Diode, Schottky, 60 V, 1 A, SOD-123F", Manufacturer="NXP Semiconductor", Supplier Part Number 1=568-4104-1-ND, Value1=1A, Value2=0.57V
D3: library part CMP-0076957-2, "Diode, Switching, 75 V, 0.3 A, SOD-523", Manufacturer="Micro Commercial Components", PartNumber=1N4148X-TP, Supplier Part Number 1=1N4148XTPMSCT-ND, Value1=0.3A, Value2=1.25V
D5: library part CMP-0028458-1, "Diode, Schottky, 30 V, 0.2 A, SOD-323", Manufacturer="Diodes Inc.", PartNumber=BAT54WS-7-F, Supplier Part Number 1=BAT54WS-FDICT-ND, Value1=0.2A, Value2=0.7V
D6: "Diode, Schottky, 30 V, 5 A, SMC", Manufacturer="Diodes Inc.", Supplier Part Number 1=B530C-FDICT-ND, Value1=5A, Value2=0.55V
D7: "Diode, Schottky, 100 V, 5 A, SMC", Manufacturer="Comchip Technology", Supplier Part Number 1=641-1124-1-ND, Value1=5A, Value2=0.85V
D11: "LED, Green, SMD", Color=green, Manufacturer="Wurth Elektronik", Supplier Part Number 1=732-4980-1-ND, Value1=W, Value2=2V
D12: "LED, Yellow, SMD", Color=yellow, Manufacturer="Wurth Elektronik", Supplier Part Number 1=732-4981-1-ND, Value1=W, Value2=2V
FID1 FID2 FID3 FID4 FID5 FID6: "Fiducial mark.  There is nothing to buy or mount.", Manufacturer=N/A
H1 H2 H3 H4 H9 H10: "Machine Screw, Round, #4-40 x 1/4, Nylon, Philips panhead", Alternate Manufacturer=-, DigiKeyPartNumber=H542-ND, Manufacturer="B&F Fastener Supply"
H5 H6 H7 H8 H11 H12: "Standoff, Hex, 1\"L #4-40 Aluminum", Manufacturer=Keystone, Supplier Part Number 1=2205K-ND
J1 J5 J13 J23 J29 J30: "Header, 100mil, 3x1, Gold, TH", Manufacturer=Samtec, Supplier Part Number 1=HTSW-103-07-G-S-ND
J2: library part CMP-0054623-1, "Header, 2.54mm, 10x2, Tin, TH", Color=Black, Current_A=3A, Manufacturer="Sullins Connector Solutions", Supplier Part Number 1=S2012E-10-ND
J3 J4 J14 J16 J27 J35 J37: "Header, 100mil, 2x1, Gold, TH", Manufacturer=Samtec, Supplier Part Number 1=SAM8736-ND
J6 J7 J8 J25 J26: library part CMP-0075484-1, "Header, 100mil, 3x1, Gold, TH", Manufacturer=Samtec, PartNumber=HTSW-103-07-G-S, Supplier Part Number 1=HTSW-103-07-G-S-ND
J9 J10 J11 J12: "Standard Banana Jack, Uninsulated, 15A", Manufacturer="Emerson Network Power", Supplier Part Number 1=J147-ND
J17: library part CMP-0075161-1, "Header(Shrouded), 2.54mm, 5x2, Gold, TH", Color=Gray, Manufacturer="Assman WSW", PartNumber=AWHW-10G-0202-T, Supplier Part Number 1=AWHW-10G-0202-T-ND
J18: library part CMP-0055096-1, "Header, 2.54 mm, 4x2, Gold, TH", Color=Black, Manufacturer=Mill-Max, Supplier Part Number 1=ED1309-08-ND
J19: library part CMP-0054590-1, "Header, 2.54mm, 8x2, Gold, TH", Color=Black, Manufacturer="Sullins Connector Solutions", Supplier Part Number 1=S2011EC-08-ND
J20: library part CMP-0065029-1, "Connector, Receptacle, USB Micro B, R/A, SMT", Color=Black, Manufacturer=FCI, Supplier Part Number 1=609-4616-1-ND
J22: "Header, 100mil, 7x1, Gold, TH", Manufacturer=Samtec, Supplier Part Number 1=SAM1029-07-ND
J28: library part CMP-0054623-2, "Header, 2.54mm, 10x2, Tin, TH", Color=Black, Current_A=3A, Manufacturer="Sullins Connector Solutions", Supplier Part Number 1=S2012E-10-ND
L1 L2 L5 L6: library part 744364410470, "Inductor, 4.7uH, SMT", Alternate Manufacturer=-, Manufacturer=WURTH
L3: "Inductor, Shielded Drum Core, Ferrite, 47 µH, 2.9 A, 0.07 ohm, SMD", Manufacturer=Coilcraft, Value1="0.07 ohm", Value2=2.9A, ValueDisplayed=47µH
L4: library part CMP-0003197-2, "Ferrite Bead, 600 ohm @ 100 MHz, 1 A, 0603", Manufacturer="Wurth Elektronik", PartNumber=742792651, Supplier Part Number 1=732-1593-1-ND, Value1="0.2 ohm", Value2=1A, ValueDisplayed="600 ohm"
L7 L8: "Ferrite Bead, 600 ohm @ 100MHz, 2A, 0805", Manufacturer=TDK, Supplier Part Number 1=445-2206-1-ND, Value1="0.1 ohm", Value2=2A
LBL1: library part THT-13-457-10, "Thermal Transfer Printable Labels, 1.250\" W x 0.250\" H - 10,000 per roll", Manufacturer=Brady, Supplier Part Number 1=04H3909
Logo2: library part Pb-Free
Logo3: library part FCC_disclaimer, "FCC_disclaimer"
LOGO4 LOGO5 LOGO7 LOGO8: library part IEC_HotSurface, "IEC 61010-1 Hot Surface Warning"
LOGO6: library part IEC_HighVoltage, "IEC 61010-1 High Voltage Warning"
NT1 NT2 NT3: "Single point connection between nets."
Q1 Q2 Q3 Q4 Q5 Q6 Q8 Q9 Q10 Q11 Q12 Q13 Q19 Q20 Q21 Q22: "MOSFET N CH 100V D2PAK", Alternate Manufacturer=-, Current - Continuous Drain (Id) @ 25°C="65A (Ta)", Input Capacitance (Ciss) @ Vds="5400pF @ 50V", Manufacturer="Toshiba Semiconductor and Storage", Power - Max=156W, Supplier Device Package=D2PAK, Supplier Part Number=TK65G10N1RQCT-ND
Q14 Q15: "MOSFET, N-CH, 100 V, 21 A, PowerPAK SO-8", Alternate Manufacturer=None, Manufacturer=Vishay-Siliconix, Supplier Part Number 1=SI7454DDP-T1-GE3CT-ND, Value1="0.047 ohm", Value2="12.8 nC"
Q16 Q17 Q18: "MOSFET, N-CH, 60 V, 0.24 A, SOT-23", Alternate Manufacturer=None, Manufacturer=Vishay-Siliconix, Supplier Part Number 1=2N7002E-T1-E3CT-ND, Value1="1.8 ohm", Value2="0.4 nC"
R1 R5 R8 R43: "RES, 95.3 k, 1%, 0.1 W, 0603", Manufacturer=Vishay-Dale, Power_W=0.1, Supplier Part Number 1=541-95.3KHCT-ND, TempCo="100 ppm/C", Tolerance_%=1, Value1=1%, Value2=0.1W, Value_Code=95k3, ValueDisplayed=95.3k
R2 R19 R23 R172: "RES, 634, 1%, 0.1 W, 0603", Manufacturer=Vishay-Dale, Power_W=0.1, Supplier Part Number 1=541-634HCT-ND, TempCo="100 ppm/C", Tolerance_%=1, Value1=1%, Value2=0.1W, Value_Code=634R, ValueDisplayed=634
R3 R9 R20 R171: "RES, 9.09 k, 1%, 0.1 W, 0603", Manufacturer=Vishay-Dale, Power_W=0.1, Supplier Part Number 1=541-9.09KHCT-ND, TempCo="100 ppm/C", Tolerance_%=1, Value1=1%, Value2=0.1W, Value_Code=9k09, ValueDisplayed=9.09k
R4 R34: library part CMP-0021990-4, "RES, 100 k, 1%, 0.1 W, AEC-Q200 Grade 0, 0603", Manufacturer=Vishay-Dale, Power_W=100mW, Supplier Part Number 1=541-100KHCT-ND, TempCo="100 ppm/C", Tolerance_%=1%, Value2=0.1W, Value_Code=100k
R6 R87: library part CMP-0022705-3, "RES, 49.9 k, 1%, 0.1 W, AEC-Q200 Grade 0, 0603", Manufacturer=Panasonic, Power_W=100mW, Supplier Part Number 1=P49.9KHCT-ND, TempCo="100 ppm/C", Tolerance_%=1%, Value2=0.1W, Value_Code=49k9, ValueDisplayed=49.9k
R7 R11 R81 R86 R89 R102 R139 R144 R148 R151 R152 R154: "RES, 10.0 k, 1%, 0.1 W, 0603", Manufacturer=Vishay-Dale, Power_W=0.1, Supplier Part Number 1=541-10.0KHCT-ND, TempCo="100 ppm/C", Tolerance_%=1, Value1=1%, Value2=0.1W, Value_Code=10k0, ValueDisplayed=10.0k
R10: library part CMP-0022680-4, "RES, 1.00 k, 1%, 0.1 W, 0603", Manufacturer=Panasonic, Power_W=100mW, Supplier Part Number 1=P1.00KHCT-ND, TempCo="100 ppm/C", Tolerance_%=1%, Value2=0.1W, Value_Code=1k00, ValueDisplayed=1.00k
R12 R157: "RES, 49.9 k, 1%, 0.1 W, 0603", Manufacturer=Vishay-Dale, Power_W=0.1, Supplier Part Number 1=541-49.9KHCT-ND, TempCo="100 ppm/C", Tolerance_%=1, Value1=1%, Value2=0.1W, Value_Code=49k9, ValueDisplayed=49.9k
R13 R158: "RES, 40.2 k, 1%, 0.1 W, 0603", Manufacturer=Vishay-Dale, Power_W=0.1, Supplier Part Number 1=541-40.2KHCT-ND, TempCo="100 ppm/C", Tolerance_%=1, Value1=1%, Value2=0.1W, Value_Code=40k2, ValueDisplayed=40.2k
R14 R159: "RES, 24.9, 1%, 0.125 W, 0805", Manufacturer=Vishay-Dale, Power_W=0.125, Supplier Part Number 1=541-24.9CCT-ND, TempCo="100 ppm/C", Tolerance_%=1, Value1=1%, Value2=0.125W, Value_Code=24R9, ValueDisplayed=24.9
R15 R167: library part CMP-0022700-3, "RES, 40.2 k, 1%, 0.1 W, AEC-Q200 Grade 0, 0603", Manufacturer=Panasonic, Power_W=100mW, Supplier Part Number 1=P40.2KHDKR-ND, TempCo="100 ppm/C", Tolerance_%=1%, Value2=0.1W, Value_Code=40k2, ValueDisplayed=40.2k
R16: library part CMP-0080414-1, "RES, 0.001, 1%, 7 W, AEC-Q200 Grade 0, 6.6x3x6.9mm", Manufacturer=Vishay-Dale, Power_W=7W, Supplier Part Number 1=WSLP27261L000FEA-ND, TempCo="75 ppm/C", Tolerance_%=1%, Value_Code=1L000, ValueDisplayed=0.001
R17 R169: "RES, 51.1 k, 1%, 0.1 W, 0603", Manufacturer=Vishay-Dale, Power_W=0.1, Supplier Part Number 1=541-51.1KHCT-ND, TempCo="100 ppm/C", Tolerance_%=1, Value1=1%, Value2=0.1W, Value_Code=51k1, ValueDisplayed=51.1k
R18 R170: "RES, 54.9 k, 1%, 0.1 W, 0603", Manufacturer=Vishay-Dale, Power_W=0.1, Supplier Part Number 1=541-54.9KHCT-ND, TempCo="100 ppm/C", Tolerance_%=1, Value1=1%, Value2=0.1W, Value_Code=54k9, ValueDisplayed=54.9k
R21 R32 R173 R184: "RES, 0.001, 1%, 3 W, 6.6x3x6.9mm", Manufacturer=Vishay-Dale, Power_W=3, Supplier Part Number 1=WSLQ-.001CT-ND, TempCo="75 ppm/C", Tolerance_%=1, Value1=1%, Value2=3W, Value_Code=1L000, ValueDisplayed=0.001
R22 R24 R25 R29 R33 R35 R36 R40 R174 R175 R176 R182 R185 R188 R189 R193: "RES, 49.9 k, 1%, 0.125 W, 0805", Manufacturer=Vishay-Dale, Power_W=0.125, Supplier Part Number 1=541-49.9KCCT-ND, TempCo="100 ppm/C", Tolerance_%=1, Value1=1%, Value2=0.125W, Value_Code=49k9, ValueDisplayed=49.9k
R26 R27 R28 R30 R37 R38 R39 R41 R179 R180 R181 R183 R190 R191 R192 R194: "RES, 1.00, 1%, 0.125 W, 0805", Manufacturer=Vishay-Dale, Power_W=0.125, Supplier Part Number 1=71-CRCW0805-1-E3, TempCo="100 ppm/C", Tolerance_%=1, Value1=1%, Value2=0.125W, Value_Code=1R00, ValueDisplayed=1.00
R31 R42 R56 R57 R58 R59 R177 R178 R186 R187: "RES, 1.0, 5%, 0.1 W, 0603", Manufacturer=Vishay-Dale, Power_W=0.1, Supplier Part Number 1=541-1.0GCT-ND, TempCo="200 ppm/C", Tolerance_%=5, Value1=5%, Value2=0.1W, Value_Code=1R00, ValueDisplayed=1.0
R44 R67 R72 R133 R135 R136 R147 R160 R161 R163 R164 R165 R168: library part CMP-0025874-3, "RES, 0, 5%, 0.1 W, 0603", Manufacturer=Panasonic, PartNumber=ERJ-3GEY0R00V, Power_W=100mW, Supplier Part Number 1=P0.0GCT-ND, TempCo="600 ppm/C", Tolerance_%=5%, Value2=0.1W, Value_Code=0000, ValueDisplayed=0
R45 R60: library part CMP-0023153-3, "RES, 4.70 k, 1%, 0.1 W, 0603", Manufacturer="Yageo America", Power_W=100mW, Supplier Part Number 1=311-4.70KHRCT-ND, TempCo="200 ppm/C", Tolerance_%=1%, Value2=0.1W, Value_Code=4k70, ValueDisplayed=4.70k
R46: "RES, 18.2 k, 1%, 0.1 W, 0603", Manufacturer=Vishay-Dale, Power_W=0.1, Supplier Part Number 1=541-18.2KHCT-ND, TempCo="100 ppm/C", Tolerance_%=1, Value1=1%, Value2=0.1W, Value_Code=18k2, ValueDisplayed=18.2k
R47: "RES, 0.068, 1%, 1 W, 0612", Manufacturer="Susumu Co Ltd", Power_W=1, Supplier Part Number 1=PRL1632.068FCT-ND, TempCo="50 ppm/C", Value1=1%, Value2=1W, Value_Code=R068, ValueDisplayed=0.068
R48: "RES, 24.0 k, 1%, 0.1 W, 0603", Manufacturer="Yageo America", Power_W=0.1, Supplier Part Number 1=311-24.0KHRCT-ND, TempCo="200 ppm/C", Tolerance_%=1, Value1=1%, Value2=0.1W, Value_Code=24k0, ValueDisplayed=24.0k
R49: library part CMP-0023278-3, "RES, 7.32 k, 1%, 0.1 W, 0603", Manufacturer="Yageo America", Power_W=100mW, Supplier Part Number 1=311-7.32KHRCT-ND, TempCo="200 ppm/C", Tolerance_%=1%, Value2=0.1W, Value_Code=7k32, ValueDisplayed=7.32k
R50: library part CMP-0023172-3, "RES, 52.3 k, 1%, 0.1 W, 0603", Manufacturer="Yageo America", Power_W=100mW, Supplier Part Number 1=311-52.3KHRCT-ND, TempCo="200 ppm/C", Tolerance_%=1%, Value2=0.1W, Value_Code=52k3, ValueDisplayed=52.3k
R51: "RES, 10.0, 1%, 0.1 W, 0603", Manufacturer=Vishay-Dale, Power_W=0.1, Supplier Part Number 1=541-10.0HCT-ND, TempCo="100 ppm/C", Tolerance_%=1, Value1=1%, Value2=0.1W, Value_Code=10R0, ValueDisplayed=10.0
R52 R73: library part CMP-0022749-2, "RES, 10.5, 1%, 0.1 W, 0603", Manufacturer="Yageo America", Power_W=100mW, Supplier Part Number 1=311-10.5HRCT-ND, TempCo="200 ppm/C", Tolerance_%=1%, Value2=0.1W, Value_Code=10R5, ValueDisplayed=10.5
R53 R101: "RES, 20.0 k, 1%, 0.1 W, 0603", Manufacturer=Vishay-Dale, Power_W=0.1, Supplier Part Number 1=541-20.0KHCT-ND, TempCo="100 ppm/C", Tolerance_%=1, Value1=1%, Value2=0.1W, Value_Code=20k0, ValueDisplayed=20.0k
R54 R55 R95 R166: "RES, 2.0, 5%, 0.125 W, 0805", Manufacturer=Vishay-Dale, Power_W=0.125, Supplier Part Number 1=541-2.0ACT-ND, TempCo="200 ppm/C", Tolerance_%=5, Value1=5%, Value2=0.125W, Value_Code=2R00, ValueDisplayed=2.0
R61 R62 R63 R64: library part CMP-0021998-4, "RES, 10.0 k, 1%, 0.1 W, AEC-Q200 Grade 0, 0603", Manufacturer=Vishay-Dale, PartNumber=CRCW060310K0FKEA, Power_W=100mW, Supplier Part Number 1=541-10.0KHCT-ND, TempCo="100 ppm/C", Tolerance_%=1%, Value2=0.1W, Value_Code=10k0, ValueDisplayed=10.0k
R65 R68 R69 R71 R120 R195: library part CMP-0022446-5, "RES, 499, 1%, 0.1 W, AEC-Q200 Grade 0, 0603", Manufacturer=Vishay-Dale, PartNumber=CRCW0603499RFKEA, Power_W=100mW, Supplier Part Number 1=541-499HCT-ND, TempCo="100 ppm/C", Tolerance_%=1%, Value2=0.1W, Value_Code=499R, ValueDisplayed=499
R70: library part CMP-0023872-3, "RES, 1.15 k, 0.1%, 0.1 W, 0603", Manufacturer="Yageo America", PartNumber=RT0603BRD071K15L, Power_W=100mW, TempCo="25 ppm/C", Tolerance_%=0.1%, Value2=0.1W, Value_Code=1k15
R74 R93: library part CMP-0022746-3, "RES, 10.0 k, 1%, 0.1 W, 0603", Manufacturer="Yageo America", PartNumber=RC0603FR-0710KL, Power_W=100mW, Supplier Part Number 1=311-10.0KHRCT-ND, TempCo="200 ppm/C", Tolerance_%=1%, Value2=0.1W, Value_Code=10k0, ValueDisplayed=10.0k
R76: "RES, 4.42 k, 1%, 0.1 W, 0603", Manufacturer=Vishay-Dale, Power_W=0.1, Supplier Part Number 1=541-4.42KHCT-ND, TempCo="100 ppm/C", Tolerance_%=1, Value1=1%, Value2=0.1W, Value_Code=4k42, ValueDisplayed=4.42k
R78: "RES, 26.7 k, 1%, 0.1 W, 0603", Manufacturer=Vishay-Dale, Power_W=0.1, Supplier Part Number 1=541-26.7KHCT-ND, TempCo="100 ppm/C", Tolerance_%=1, Value1=1%, Value2=0.1W, Value_Code=26k7, ValueDisplayed=26.7k
R80: library part CMP-0022109-5, "RES, 1.00 k, 1%, 0.1 W, AEC-Q200 Grade 0, 0603", Manufacturer=Vishay-Dale, Power_W=100mW, Supplier Part Number 1=541-1.00KHCT-ND, TempCo="100 ppm/C", Tolerance_%=1%, Value2=0.1W, Value_Code=1k00, ValueDisplayed=1.00k
R82: library part CMP-0022895-3, "RES, 1.00 k, 1%, 0.1 W, 0603", Manufacturer="Yageo America", PartNumber=RC0603FR-071KL, Power_W=100mW, Supplier Part Number 1=311-1.00KHRCT-ND, TempCo="200 ppm/C", Tolerance_%=1%, Value2=0.1W, Value_Code=1k00, ValueDisplayed=1.00k
R84: library part CMP-0022731-2, "RES, 1.00 M, 1%, 0.125 W, 0603", Manufacturer=Vishay/Beyschlag, Power_W=125mW, Supplier Part Number 1=MCT0603-1.00M-CFCT-ND, TempCo="50 ppm/C", Tolerance_%=1%, Value2=0.125W, Value_Code=1M00, ValueDisplayed=1.00M
R90 R91: "RES, 4.99 k, 1%, 0.1 W, 0603", Manufacturer=Vishay-Dale, Power_W=0.1, Supplier Part Number 1=541-4.99KHCT-ND, TempCo="100 ppm/C", Tolerance_%=1, Value1=1%, Value2=0.1W, Value_Code=4k99, ValueDisplayed=4.99k
R92 R94 R155 R156: library part CMP-0022684-3, "RES, 10.0 k, 1%, 0.1 W, 0603", Manufacturer=Panasonic, Power_W=100mW, Supplier Part Number 1=P10.0KHCT-ND, TempCo="100 ppm/C", Tolerance_%=1%, Value2=0.1W, Value_Code=10k0, ValueDisplayed=10.0k
R96: library part CMP-0022717-2, "RES, 0.51, 1%, 0.1 W, AEC-Q200 Grade 1, 0603", Manufacturer=Panasonic, PartNumber=ERJ-3RQFR51V, Power_W=100mW, Supplier Part Number 1=P.51AJCT-ND, TempCo="300 ppm/C", Tolerance_%=1%, Value2=0.1W, Value_Code=R510, ValueDisplayed=0.51
R99: library part CMP-0025701-4, "RES, 10 k, 5%, 0.1 W, AEC-Q200 Grade 0, 0603", Manufacturer=Vishay-Dale, PartNumber=CRCW060310K0JNEA, Power_W=100mW, Supplier Part Number 1=541-10KGCT-ND, TempCo="200 ppm/C", Tolerance_%=5%, Value2=0.1W, Value_Code=10k0, ValueDisplayed=10k
R111 R112 R114 R117 R124 R132: library part CMP-0022883-3, "RES, 1.50 k, 1%, 0.1 W, 0603", Manufacturer="Yageo America", Power_W=100mW, Supplier Part Number 1=311-1.50KHRCT-ND, TempCo="200 ppm/C", Tolerance_%=1%, Value2=0.1W, Value_Code=1k50, ValueDisplayed=1.50k
R113 R115 R128 R130: library part CMP-0022448-4, "RES, 49.9, 1%, 0.1 W, AEC-Q200 Grade 0, 0603", Manufacturer=Vishay-Dale, PartNumber=CRCW060349R9FKEA, Power_W=100mW, Supplier Part Number 1=541-49.9HCT-ND, TempCo="100 ppm/C", Tolerance_%=1%, Value2=0.1W, Value_Code=49R9, ValueDisplayed=49.9
R116 R121 R122 R123 R131: library part CMP-0021990-4, "RES, 100 k, 1%, 0.1 W, AEC-Q200 Grade 0, 0603", Manufacturer=Vishay-Dale, PartNumber=CRCW0603100KFKEA, Power_W=100mW, Supplier Part Number 1=541-100KHCT-ND, TempCo="100 ppm/C", Tolerance_%=1%, Value2=0.1W, Value_Code=100k
R118 R119 R125 R127: library part CMP-0021991-4, "RES, 100, 1%, 0.1 W, AEC-Q200 Grade 0, 0603", Manufacturer=Vishay-Dale, PartNumber=CRCW0603100RFKEA, Power_W=100mW, Supplier Part Number 1=541-100HCT-ND, TempCo="100 ppm/C", Tolerance_%=1%, Value2=0.1W, Value_Code=100R, ValueDisplayed=100
R126 R129: library part CMP-0023081-3, "RES, 3.30 k, 1%, 0.1 W, 0603", Manufacturer="Yageo America", Power_W=100mW, Supplier Part Number 1=311-3.30KHRCT-ND, TempCo="200 ppm/C", Tolerance_%=1%, Value2=0.1W, Value_Code=3k30, ValueDisplayed=3.30k
R134: library part CMP-0022170-4, "RES, 1.00, 1%, 0.1 W, AEC-Q200 Grade 0, 0603", Manufacturer=Vishay-Dale, PartNumber=CRCW06031R00FKEA, Power_W=100mW, Supplier Part Number 1=52K8059, TempCo="100 ppm/C", Tolerance_%=1%, Value2=0.1W, Value_Code=1R00, ValueDisplayed=1.00
R137: library part CMP-0022138-4, "RES, 1.00 M, 1%, 0.1 W, AEC-Q200 Grade 0, 0603", Manufacturer=Vishay-Dale, PartNumber=CRCW06031M00FKEA, Power_W=100mW, Supplier Part Number 1=541-1.00MHCT-ND, TempCo="100 ppm/C", Tolerance_%=1%, Value2=0.1W, Value_Code=1M00, ValueDisplayed=1.00M
R138: library part CMP-0022109-5, "RES, 1.00 k, 1%, 0.1 W, AEC-Q200 Grade 0, 0603", Manufacturer=Vishay-Dale, PartNumber=CRCW06031K00FKEA, Power_W=100mW, Supplier Part Number 1=541-1.00KHCT-ND, TempCo="100 ppm/C", Tolerance_%=1%, Value2=0.1W, Value_Code=1k00, ValueDisplayed=1.00k
R140 R150: "RES, 1.00 M, 1%, 0.1 W, 0603", Manufacturer=Vishay-Dale, Power_W=0.1, Supplier Part Number 1=541-1.00MHCT-ND, TempCo="100 ppm/C", Tolerance_%=1, Value1=1%, Value2=0.1W, Value_Code=1M00, ValueDisplayed=1.00M
R141: "RES, 100, 1%, 0.1 W, 0603", Manufacturer=Vishay-Dale, Power_W=0.1, Supplier Part Number 1=541-100HCT-ND, TempCo="100 ppm/C", Tolerance_%=1, Value1=1%, Value2=0.1W, Value_Code=100R, ValueDisplayed=100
